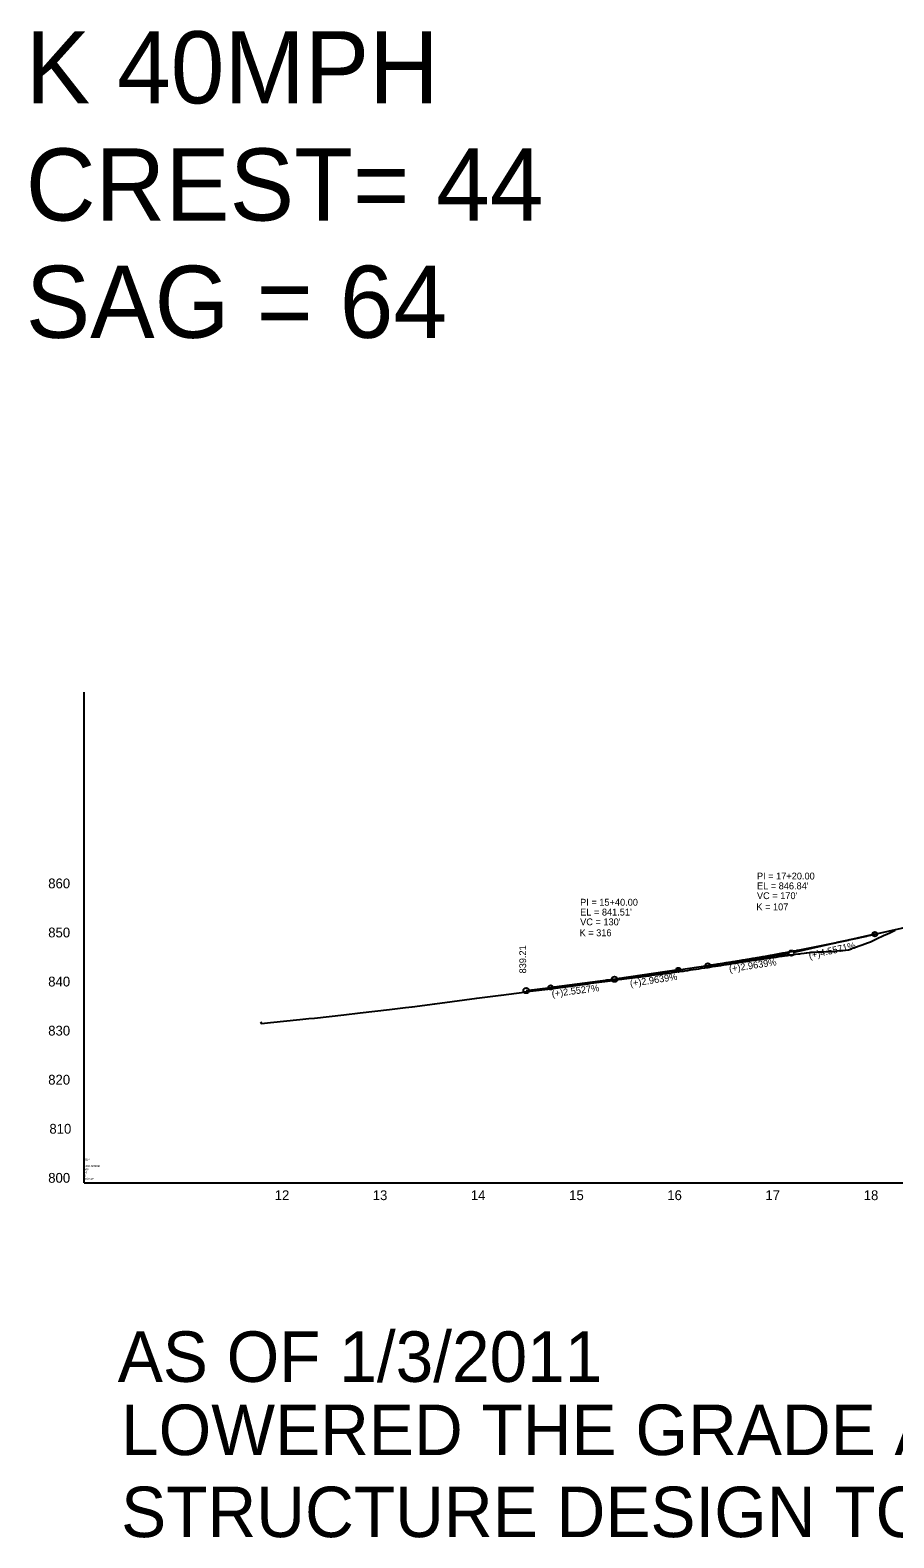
# Model space of a CAD drawing. Extents: x 570622 to 580296, y -55533 to -48575.
# Drawn here: x 573743 to 574622, y -53797 to -52261 of the extents above; entities that cross this region are included whole.
import ezdxf

# ---------------------------------------------------------------- set-up
doc = ezdxf.new("R2010")
doc.units = 0
for name, color, linetype in [('Default', 7, 'Continuous'), ('Exist Profile Cell', 7, 'Continuous'), ('Exist Vertical Profile Ground Line', 7, 'Continuous'), ('Exist Vertical Profile Horizontal Axis Label Major', 7, 'Continuous'), ('Exist Vertical Profile Vertical Axis Label', 7, 'Continuous'), ('Prop Vertical Profile Curve Label', 7, 'Continuous'), ('Prop Vertical Profile Grade', 7, 'Continuous'), ('Prop Vertical Profile Grade Label', 7, 'Continuous'), ('Prop VPI Label', 7, 'Continuous')]:
    doc.layers.add(name, color=color, linetype=linetype)

msp = doc.modelspace()

# ---------------------------------------------------------------- linework, layer by layer
at = {"layer": 'Exist Profile Cell'}
for q in [(573797.6, -52935.4), (576393.8, -53435.4), (573797.6, -53435.4)]:
    msp.add_line((573797.6, -53435.4), q, dxfattribs=at)
at = {"layer": 'Exist Vertical Profile Ground Line'}
for points in [[(574493.8, -53206.4), (574495.9, -53206.1), (574496.7, -53206), (574499.5, -53205.6), (574502.3, -53205.2), (574505.1, -53204.8), (574507.9, -53204.4), (574508.4, -53204.3), (574510.7, -53204), (574513.6, -53203.6), (574516.4, -53203.1), (574516.9, -53203), (574519.2, -53202.8), (574522, -53202.4), (574524.8, -53202.1), (574526.3, -53201.9), (574527.6, -53201.7), (574530.5, -53201.4), (574532.9, -53201), (574533.3, -53201), (574536.1, -53200.6), (574537.8, -53200.4), (574538.9, -53200.3), (574541.7, -53200.2), (574544.5, -53200), (574547.4, -53199.9), (574550.2, -53199.8), (574553, -53199.7), (574555.8, -53199.6), (574558.6, -53199.5), (574559, -53199.5), (574561.5, -53199.3), (574564.3, -53199), (574567.1, -53198.7), (574569.9, -53198.4), (574572.7, -53198.1), (574575.7, -53197.8), (574578.9, -53196.8), (574579.2, -53196.7), (574579.9, -53196.3), (574581.2, -53195.9), (574584, -53194.9), (574586.8, -53193.8), (574589.6, -53192.8), (574592.4, -53191.8), (574595.3, -53190.7), (574598.1, -53189.6), (574599.5, -53189.1), (574600.9, -53188.4), (574603.7, -53187.1), (574606.5, -53185.8), (574609.3, -53184.4), (574610.8, -53183.7), (574612.2, -53183.1), (574615, -53181.8), (574617.8, -53180.6), (574620.6, -53179.3), (574623.4, -53178)], [(573977.2, -53271.1), (573978, -53272.8), (573987.2, -53272), (574017.1, -53269), (574026.5, -53268), (574032.1, -53267.5), (574062.1, -53264.1), (574078.5, -53262.2), (574108.4, -53258.6), (574124.8, -53256.7), (574131.6, -53255.8), (574154.8, -53252.8), (574172.4, -53250.6), (574197.3, -53247.2), (574221.7, -53244), (574222.2, -53243.9), (574245.7, -53240.9), (574246, -53240.8), (574269.8, -53237.9), (574293, -53234.9), (574307.9, -53232.8), (574310.7, -53232.4), (574313.5, -53232), (574315.7, -53231.6), (574316.4, -53231.6), (574319.2, -53231.2), (574322, -53230.8), (574324.8, -53230.4), (574327.6, -53230.1), (574330.4, -53229.7), (574333.3, -53229.3), (574336.1, -53229), (574338.9, -53228.6), (574341.7, -53228.2), (574344.5, -53227.8), (574345, -53227.8), (574347.4, -53227.5), (574350.2, -53227.1), (574353, -53226.7), (574355.8, -53226.4), (574358.6, -53226), (574361.4, -53225.7), (574361.9, -53225.6), (574364.3, -53225.3), (574367.1, -53224.9), (574369.9, -53224.6), (574372.7, -53224.2), (574375.5, -53223.8), (574378.3, -53223.5), (574381.2, -53223.1), (574382.6, -53222.9), (574384, -53222.7), (574384.9, -53222.6), (574386.8, -53222.3), (574389.6, -53222), (574392.4, -53221.6), (574395.2, -53221.2), (574398.1, -53220.8), (574400.9, -53220.4), (574403.4, -53220.1), (574403.7, -53220), (574406.5, -53219.7), (574407.8, -53219.5), (574409.3, -53219.3), (574412.1, -53218.8), (574415, -53218.4), (574417.8, -53218), (574420.6, -53217.5), (574423.1, -53217.2), (574423.4, -53217.1), (574426.2, -53216.7), (574429, -53216.3), (574429.5, -53216.2), (574431.9, -53215.8), (574434.7, -53215.4), (574437.5, -53215), (574440.3, -53214.5), (574442.1, -53214.3), (574443.1, -53214.1), (574445.9, -53213.7), (574448.8, -53213.2), (574451.1, -53212.9), (574451.6, -53212.8), (574454.4, -53212.4), (574457.2, -53211.9), (574460, -53211.5), (574461, -53211.4), (574462.9, -53211.1), (574465.7, -53210.6), (574468.5, -53210.2), (574471.3, -53209.8), (574473.5, -53209.5), (574474.1, -53209.4), (574476.9, -53208.9), (574479.8, -53208.5), (574482.6, -53208.1), (574485.4, -53207.7), (574488.2, -53207.3), (574491, -53206.8), (574492.6, -53206.6), (574493.8, -53206.4)]]:
    msp.add_lwpolyline(points, dxfattribs=at)
at = {"layer": 'Prop Vertical Profile Curve Label'}
for centre in [(574602.6, -53181.9), (574432.6, -53213.8), (574402.6, -53218.3), (574272.6, -53236.2)]:
    msp.add_circle(centre, 2.25, dxfattribs=at)
at = {"layer": 'Prop Vertical Profile Grade'}
for p, q in [((574602.6, -53181.9), (574685.1, -53163.1)), ((574402.6, -53218.3), (574432.6, -53213.8)), ((574247.6, -53239.4), (574272.6, -53236.2))]:
    msp.add_line(p, q, dxfattribs=at)
for points in [[(574432.6, -53213.8), (574436, -53213.3), (574439.4, -53212.8), (574442.8, -53212.3), (574446.2, -53211.8), (574449.6, -53211.2), (574453, -53210.7), (574456.4, -53210.2), (574459.8, -53209.6), (574463.2, -53209.1), (574466.6, -53208.5), (574470, -53207.9), (574473.4, -53207.4), (574476.8, -53206.8), (574480.2, -53206.2), (574483.6, -53205.7), (574487, -53205.1), (574490.4, -53204.5), (574493.8, -53203.9), (574497.2, -53203.3), (574500.6, -53202.7), (574504, -53202), (574507.4, -53201.4), (574510.8, -53200.8), (574514.2, -53200.2), (574517.6, -53199.5), (574521, -53198.9), (574524.4, -53198.2), (574527.8, -53197.6), (574531.2, -53196.9), (574534.6, -53196.3), (574538, -53195.6), (574541.4, -53194.9), (574544.8, -53194.2), (574548.2, -53193.6), (574551.6, -53192.9), (574555, -53192.2), (574558.4, -53191.5), (574561.8, -53190.8), (574565.2, -53190), (574568.6, -53189.3), (574572, -53188.6), (574575.4, -53187.9), (574578.8, -53187.1), (574582.2, -53186.4), (574585.6, -53185.7), (574589, -53184.9), (574592.4, -53184.2), (574595.8, -53183.4), (574599.2, -53182.6), (574602.6, -53181.9)], [(574272.6, -53236.2), (574275.2, -53235.9), (574277.8, -53235.5), (574280.4, -53235.2), (574283, -53234.9), (574285.6, -53234.5), (574288.2, -53234.2), (574290.8, -53233.8), (574293.4, -53233.5), (574296, -53233.2), (574298.6, -53232.8), (574301.2, -53232.5), (574303.8, -53232.1), (574306.4, -53231.8), (574309, -53231.4), (574311.6, -53231.1), (574314.2, -53230.7), (574316.8, -53230.4), (574319.4, -53230), (574322, -53229.7), (574324.6, -53229.3), (574327.2, -53229), (574329.8, -53228.6), (574332.4, -53228.3), (574335, -53227.9), (574337.6, -53227.6), (574340.2, -53227.2), (574342.8, -53226.8), (574345.4, -53226.5), (574348, -53226.1), (574350.6, -53225.8), (574353.2, -53225.4), (574355.8, -53225), (574358.4, -53224.7), (574361, -53224.3), (574363.6, -53223.9), (574366.2, -53223.6), (574368.8, -53223.2), (574371.4, -53222.8), (574374, -53222.4), (574376.6, -53222.1), (574379.2, -53221.7), (574381.8, -53221.3), (574384.4, -53220.9), (574387, -53220.6), (574389.6, -53220.2), (574392.2, -53219.8), (574394.8, -53219.4), (574397.4, -53219), (574400, -53218.6), (574402.6, -53218.3)]]:
    msp.add_spline(points, degree=3, dxfattribs=at)
at = {"layer": 'Prop VPI Label'}
for p, q in [((574602.6, -53181.9), (574520.3, -53200.6)), ((574432.6, -53213.8), (574514.9, -53201.6)), ((574272.6, -53236.2), (574334.9, -53228.2)), ((574402.6, -53218.3), (574340.3, -53227.5))]:
    msp.add_line(p, q, dxfattribs=at)
for centre in [(574517.6, -53201.2), (574337.6, -53227.9), (574247.6, -53239.4), (574247.6, -53239.4)]:
    msp.add_circle(centre, 2.75, dxfattribs=at)

# ---------------------------------------------------------------- texts
at = {"layer": 'Default'}
for s, height, p in [('K 40MPH', 73.5, (573738.2, -52335.4)), ('CREST= 44', 73.5, (573738.2, -52454.8)), ('SAG = 64', 73.5, (573738.2, -52574.3)), ('AS OF 1/3/2011', 51.45, (573831.8, -53638.1)), ('LOWERED THE GRADE AS REQUESTED BY ', 51.45, (573835.2, -53712.7)), ('STRUCTURE DESIGN TO SHORTEN BRIDGE', 51.45, (573835.2, -53796.3))]:
    msp.add_text(s, height=height, dxfattribs=at).set_placement(p)
at = {"layer": 'Exist Profile Cell'}
for s, p in [('RDY', (573797.6, -53412.7)), ('L', (573797.6, -53415.9)), ('800', (573797.6, -53422.4)), ('1000.000000', (573797.6, -53419.2)), ('10', (573797.6, -53425.7)), ('2', (573797.6, -53428.9)), ('NOGAP', (573797.6, -53432.2))]:
    msp.add_text(s, height=2, dxfattribs=at).set_placement(p)
at = {"layer": 'Exist Vertical Profile Horizontal Axis Label Major'}
for s, p in [('12', (573991.6, -53452.9)), ('13', (574091.4, -53452.9)), ('14', (574191.3, -53452.9)), ('15', (574291.4, -53452.9)), ('16', (574391.3, -53452.9)), ('17', (574491.2, -53452.9)), ('18', (574591.3, -53452.9))]:
    msp.add_text(s, height=10, dxfattribs=at).set_placement(p)
at = {"layer": 'Exist Vertical Profile Vertical Axis Label'}
for s, p in [('860', (573761, -53135.2)), ('850', (573761, -53185.2)), ('840', (573761, -53235.2)), ('830', (573761, -53285.2)), ('820', (573761, -53335.2)), ('810', (573762.2, -53385.2)), ('800', (573761, -53435.2))]:
    msp.add_text(s, height=10, dxfattribs=at).set_placement(p)
at = {"layer": 'Prop Vertical Profile Curve Label'}
for s, p in [("VC = 170'", (574482.6, -53146.2)), ('K = 107', (574482, -53157.6)), ("VC = 130'", (574302.6, -53172.9)), ('K = 316', (574302, -53184))]:
    msp.add_text(s, height=7, dxfattribs=at).set_placement(p)
at = {"layer": 'Prop Vertical Profile Grade Label'}
for s, rotation, p in [('(+)4.5571%', 12.8361, (574536.2, -53207.3)), ('(+)2.9639%', 8.4296, (574454.7, -53220.7)), ('(+)2.9639%', 8.4296, (574353.8, -53235.6)), ('(+)2.5527%', 7.2735, (574274.1, -53246.1))]:
    msp.add_text(s, height=7, rotation=rotation, dxfattribs=at).set_placement(p)
at = {"layer": 'Prop VPI Label'}
for s, p in [('PI = 17+20.00', (574482.6, -53126.2)), ("EL = 846.84'", (574482.6, -53136.2)), ('PI = 15+40.00', (574302.6, -53152.9)), ("EL = 841.51'", (574302.6, -53162.9))]:
    msp.add_text(s, height=7, dxfattribs=at).set_placement(p)
msp.add_text('839.21', height=7, rotation=90, dxfattribs=at).set_placement((574247.6, -53221.9))
msp.add_text('839.21', height=7, rotation=90, dxfattribs=at).set_placement((574247.6, -53221.9))

doc.saveas('drawing.dxf')
